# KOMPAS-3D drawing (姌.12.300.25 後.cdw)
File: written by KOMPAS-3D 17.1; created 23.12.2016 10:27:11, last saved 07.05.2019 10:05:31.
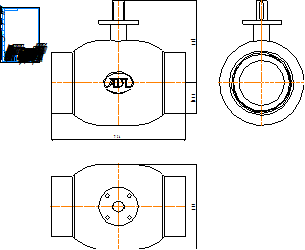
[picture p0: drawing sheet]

Sheet 1: A4, portrait

Title block, sheet 1: name: КШ.12.300.25 сс; material: Внимание! Данный продукт является объектом авторского права ООО «Торговый Дом АДЛ». / Запрещается изменение, копирование, распространение / (в том числе путем копирования на другие сайты и ресурсы в Интернете) / или любое иное использование информации и объектов без предварительного / согласия правообладателя (ООО «Торговый Дом АДЛ»).; sheets: 1; organisation: ООО "Торговый дом АДЛ"; sheet format: A4; stored path: C:\Users\tra\Desktop\2д чертежи\Шаровые краны БИВАЛ\КШ_Бивал_серия_11_12\KOMPAS_2D\КШ.12.300.25 сс.cdw

Views: Вид 1, Проекционный вид 2, Проекционный вид 3
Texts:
  Klimkovich
  ADL
Dimensions and other numbers on the sheet: 724; 441; 162,5; 457; 1:1; 1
